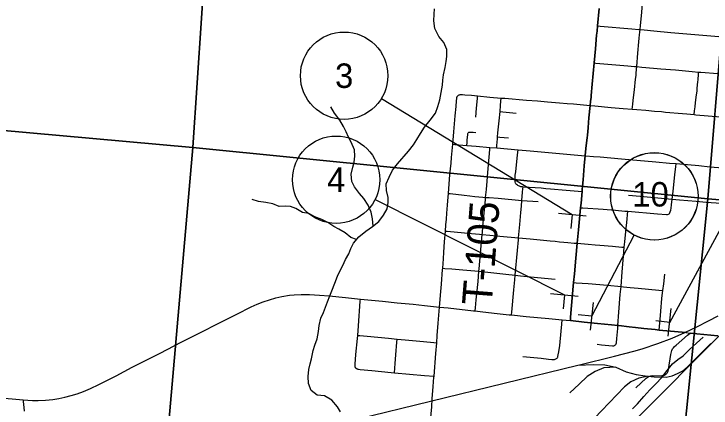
# Model space of a CAD drawing. Extents: x 0 to 1067, y 0 to 440.
# Drawn here: x 268.9 to 348.6, y 95.6 to 140.8 of the extents above; entities that cross this region are included whole.
import ezdxf

# ---------------------------------------------------------------- set-up
doc = ezdxf.new("R2010")
doc.units = 0
for name, color, linetype in [('Default', 7, 'Continuous'), ('GM_X_City_Street', 7, 'Continuous'), ('GM_X_County_Road', 7, 'Continuous'), ('GM_X_Minor_River', 7, 'Continuous'), ('GM_X_Rail_Line', 7, 'Continuous'), ('GM_X_Section', 7, 'Continuous'), ('GM_X_State_Route', 7, 'Continuous'), ('GM_X_Township_Road', 7, 'Continuous'), ('GM_X_Township_Road_Text', 7, 'Continuous'), ('GM_X_US_Route', 7, 'Continuous'), ('SH_Masking', 7, 'Continuous'), ('SH_Text', 7, 'Continuous'), ('SN_P_Signs', 7, 'Continuous')]:
    doc.layers.add(name, color=color, linetype=linetype)

msp = doc.modelspace()

# ---------------------------------------------------------------- linework, layer by layer
at = {"layer": 'Default'}
for q in [(342.702, 104.581), (346.241, 104.236)]:
    msp.add_line((345.76, 104.287), q, dxfattribs=at)
for points in [[(332.539, 105.663), (332.569, 106.043), (332.878, 109.593), (332.917, 110.017), (333.012, 111.021), (333.174, 112.817), (333.319, 114.507), (333.452, 116.059), (333.706, 118.572), (333.761, 119.12), (333.888, 120.454), (333.909, 120.678), (334.011, 121.791), (334.137, 123.39), (334.17, 123.8), (334.242, 124.531), (334.247, 124.578), (334.359, 125.704), (334.444, 126.578), (334.483, 126.899), (334.56, 127.715), (334.617, 128.333), (334.671, 128.886), (334.813, 130.281), (334.859, 130.735), (334.906, 131.249), (334.922, 131.434), (335.027, 132.729), (335.255, 135.163), (335.405, 136.764), (335.544, 138.325), (335.592, 138.808), (335.65, 139.404), (335.843, 141.399)], [(337.977, 105.1), (337.228, 105.175), (335.641, 105.333), (334.136, 105.486), (332.539, 105.663)], [(342.702, 104.581), (342.235, 104.626), (340.941, 104.771), (339.978, 104.883), (339.274, 104.963), (338.088, 105.089), (337.977, 105.1)], [(349.421, 103.902), (346.994, 104.157), (346.241, 104.236)]]:
    msp.add_lwpolyline(points, dxfattribs=at)
at = {"layer": 'GM_X_City_Street'}
for p, q in [((323.327, 125.486), (324.12, 125.418)), ((324.12, 125.418), (326.573, 125.206))]:
    msp.add_line(p, q, dxfattribs=at)
for points in [[(339.625, 129.863), (339.651, 130.082), (339.698, 130.473), (339.778, 131.215), (339.876, 132.058), (340.006, 133.278), (340.05, 133.721), (340.071, 134.016), (340.127, 134.738), (340.261, 136.274), (340.374, 137.568), (340.406, 137.974), (340.447, 138.381), (340.511, 138.974), (340.565, 139.454), (340.638, 140.158), (340.711, 140.948), (340.803, 141.959), (340.845, 142.489), (340.864, 142.724)], [(335.65, 139.404), (335.951, 139.377), (339.567, 139.051), (340.386, 138.984), (340.511, 138.974), (340.978, 138.936), (342.092, 138.84), (344.018, 138.654), (349.998, 138.146), (353.662, 137.79), (354.09, 137.748)], [(335.255, 135.163), (335.464, 135.145), (339.102, 134.824), (339.88, 134.76), (340.127, 134.738), (340.731, 134.686), (342.066, 134.561), (342.88, 134.484), (344.583, 134.346), (346.458, 134.184), (347.218, 134.115), (347.454, 134.094), (349.403, 133.93)], [(346.707, 129.236), (346.754, 129.652), (346.807, 130.116), (346.875, 130.62), (346.983, 131.498), (347.033, 131.934), (347.065, 132.258), (347.133, 132.994), (347.149, 133.209), (347.198, 133.855), (347.218, 134.115)], [(319.754, 131.469), (319.808, 131.494), (319.868, 131.513), (319.931, 131.528), (320.001, 131.538), (320.049, 131.54), (320.099, 131.538), (320.208, 131.533), (320.476, 131.513), (321.234, 131.453), (321.929, 131.379), (323.311, 131.251), (324.627, 131.139), (325.058, 131.103), (327.51, 130.9), (328.774, 130.804), (329.927, 130.71), (331.3, 130.594), (332.192, 130.528), (332.898, 130.474), (334.049, 130.359), (334.813, 130.281), (335.346, 130.227), (337.202, 130.071), (338.572, 129.955), (339.625, 129.863), (340.131, 129.818), (341.172, 129.731), (342.175, 129.642), (342.954, 129.581), (343.433, 129.537), (345.38, 129.351), (345.861, 129.312), (346.707, 129.236), (346.901, 129.218), (351.111, 128.853)], [(321.708, 128.959), (321.797, 129.972), (321.901, 131.079), (321.929, 131.379)], [(324.12, 125.418), (324.142, 125.695), (324.203, 126.457), (324.221, 126.692), (324.257, 127.16), (324.405, 128.526), (324.497, 129.581), (324.549, 130.267), (324.594, 130.771), (324.627, 131.139)], [(324.497, 129.581), (324.806, 129.55), (326.327, 129.401)], [(320.712, 125.709), (320.728, 126.047), (320.744, 126.349), (320.794, 126.934), (320.805, 127.021), (320.824, 127.095), (320.851, 127.15), (320.886, 127.186), (320.927, 127.212), (320.971, 127.23), (321.017, 127.24), (321.108, 127.236), (321.407, 127.215), (321.721, 127.192)], [(324.221, 126.692), (324.48, 126.67), (325.475, 126.585)], [(319.076, 125.847), (319.304, 125.827), (320.712, 125.709)], [(320.712, 125.709), (321.749, 125.622), (323.327, 125.486)], [(321.647, 106.761), (321.684, 107.12), (321.78, 108.053), (321.841, 108.722), (321.981, 110.129), (322.085, 111.318), (322.108, 111.576), (322.345, 114.221), (322.464, 115.529), (322.478, 115.696), (322.539, 116.438), (322.822, 119.512), (322.847, 119.767), (322.939, 120.66), (323.139, 123.085), (323.309, 125.258), (323.327, 125.486)], [(326.474, 121.153), (326.386, 121.222), (326.315, 121.309), (326.265, 121.408), (326.236, 121.533), (326.226, 121.662), (326.226, 121.958), (326.233, 122.18), (326.242, 122.292), (326.291, 122.67), (326.449, 124.258), (326.536, 124.922), (326.573, 125.206)], [(326.573, 125.206), (327.951, 125.087), (329.212, 124.969), (334.242, 124.531)], [(334.242, 124.531), (334.297, 124.526), (335.187, 124.447), (335.968, 124.387), (338.38, 124.181), (342.315, 123.826), (343.875, 123.695), (344.664, 123.625)], [(343.757, 117.836), (343.836, 117.883), (343.883, 117.93), (343.931, 117.993), (343.978, 118.104), (344.034, 118.317), (344.065, 118.523), (344.113, 118.918), (344.19, 119.569), (344.296, 120.447), (344.508, 122.377), (344.619, 123.266), (344.664, 123.625)], [(344.664, 123.625), (347.246, 123.396), (348.507, 123.277), (350.474, 123.111)], [(325.817, 106.304), (325.845, 106.613), (326.079, 109.178), (326.178, 110.315), (326.227, 110.863), (326.48, 113.676), (326.595, 114.901), (326.616, 115.13), (326.755, 116.646), (326.873, 118.018), (326.942, 118.755), (327, 119.413), (327.082, 120.35), (327.11, 120.732), (327.129, 120.988)], [(326.474, 121.153), (326.568, 121.106), (326.67, 121.067), (326.754, 121.043), (326.842, 121.022), (326.925, 121.006), (327.018, 120.995), (327.129, 120.988), (328.519, 120.893), (329.189, 120.848), (329.744, 120.794), (330.263, 120.756), (332.043, 120.608), (333.446, 120.491), (333.888, 120.454)], [(318.583, 120.218), (318.779, 120.195), (320.401, 120.009), (321.02, 119.941), (321.627, 119.881), (322.54, 119.796), (322.847, 119.767), (323.243, 119.74), (324.279, 119.662), (327, 119.413), (328.842, 119.282)], [(339.198, 120.018), (340.534, 119.899), (344.19, 119.569), (345.037, 119.494), (346.917, 119.328), (348.07, 119.234), (349.776, 119.115), (352.306, 118.96), (352.36, 118.957), (353.071, 118.894), (353.774, 118.823), (354.397, 118.748), (354.727, 118.699)], [(333.706, 118.572), (333.97, 118.554), (336.306, 118.402), (337.713, 118.293), (338.788, 118.198), (339.106, 118.168), (342.494, 117.882), (343.534, 117.804), (343.647, 117.812), (343.757, 117.836)], [(337.977, 105.1), (338.069, 106.614), (338.252, 108.664), (338.351, 109.564), (338.471, 111.259), (338.619, 113.05), (338.707, 114.056), (338.76, 114.664), (338.922, 116.258), (338.986, 116.871), (339.106, 118.168)], [(318.248, 115.901), (318.437, 115.884), (321.21, 115.633), (322.138, 115.559), (322.464, 115.529), (323.325, 115.449), (324.475, 115.333), (326.616, 115.13), (327.925, 115.019), (330.217, 114.791), (330.809, 114.736), (331.287, 114.683), (331.805, 114.635), (332.249, 114.595), (332.991, 114.533), (333.319, 114.507), (334.587, 114.407), (335.368, 114.35), (335.924, 114.301), (337.357, 114.171), (338.446, 114.079), (338.707, 114.056)], [(317.934, 111.65), (318.187, 111.634), (318.966, 111.585), (320.243, 111.479), (322.085, 111.318), (325.156, 110.971), (326.227, 110.863), (326.826, 110.801), (327.976, 110.68), (330.785, 110.397)], [(342.702, 104.581), (342.734, 104.976), (342.836, 106.233), (342.875, 106.734), (343.006, 108.177), (343.084, 108.846), (343.117, 109.098), (343.218, 109.876), (343.336, 110.977)], [(332.917, 110.017), (333.2, 109.998), (334.576, 109.904), (336.797, 109.714), (338.351, 109.564), (338.606, 109.537), (339.384, 109.465), (340.287, 109.366), (341.494, 109.253), (342.644, 109.143), (343.117, 109.098)], [(330.965, 101.313), (331.012, 101.354), (331.07, 101.418), (331.099, 101.47), (331.122, 101.541), (331.163, 101.72), (331.227, 102.09), (331.327, 102.792), (331.497, 104.456), (331.573, 105.264), (331.617, 105.747)], [(335.619, 102.957), (336.098, 102.894), (336.949, 102.808), (337.357, 102.776), (337.428, 102.776), (337.505, 102.788), (337.572, 102.801), (337.634, 102.832), (337.705, 102.881), (337.753, 102.937), (337.787, 103.002), (337.81, 103.107), (337.869, 103.59), (337.953, 104.766), (337.977, 105.1)], [(343.786, 100.069), (344.054, 101.778), (344.114, 102.069), (344.168, 102.251), (344.237, 102.414), (344.326, 102.557), (344.449, 102.69), (344.627, 102.843), (345.947, 103.982), (346.241, 104.236)], [(327.103, 101.554), (329.202, 101.351), (330.05, 101.259), (330.424, 101.223), (330.524, 101.215), (330.635, 101.209), (330.722, 101.215), (330.809, 101.232), (330.896, 101.267), (330.965, 101.313)], [(340.038, 97.946), (341.231, 99.086), (341.452, 99.224), (341.621, 99.302), (341.764, 99.341), (341.911, 99.358), (342.948, 99.349), (343.044, 99.354), (343.153, 99.366), (343.219, 99.378), (343.303, 99.406), (343.387, 99.445), (343.473, 99.507), (343.53, 99.551), (343.582, 99.605), (343.626, 99.664), (343.669, 99.73), (343.725, 99.862), (343.786, 100.069)], [(269.932, 96.575), (269.944, 96.412), (269.999, 95.698), (270.042, 95.286)]]:
    msp.add_lwpolyline(points, dxfattribs=at)
at = {"layer": 'GM_X_County_Road'}
for p, q in [((317.424, 105.354), (317.559, 107.21)), ((317.316, 103.968), (317.424, 105.354)), ((317.246, 103.123), (317.316, 103.968))]:
    msp.add_line(p, q, dxfattribs=at)
for points in [[(316.94, 99.297), (317.146, 101.896), (317.246, 103.123)], [(316.492, 93.735), (316.615, 94.973), (316.68, 95.792), (316.744, 96.684), (316.851, 98.118), (316.932, 99.195), (316.94, 99.297)]]:
    msp.add_lwpolyline(points, dxfattribs=at)
at = {"layer": 'GM_X_Minor_River'}
for points in [[(306.238, 95.195), (305.884, 95.771), (305.237, 96.533), (304.403, 97.049), (303.585, 97.131), (302.865, 97.645), (302.583, 98.47), (302.529, 99.245), (302.634, 100.064), (302.759, 100.7), (302.906, 101.29), (303.128, 102.22), (303.321, 102.855), (303.561, 103.557), (303.735, 104.397), (303.816, 105.079), (303.99, 105.942), (304.297, 106.575), (304.513, 107.186), (304.752, 107.82), (305.037, 108.476), (305.252, 109.065), (305.609, 109.925), (305.897, 110.74), (306.18, 111.328), (306.51, 111.983), (306.795, 112.639), (307.194, 113.316), (307.433, 113.927), (307.739, 114.514), (308.321, 115.233), (309.13, 115.88), (309.913, 116.414), (310.63, 117.017), (311.166, 117.714), (311.566, 118.437), (311.693, 119.186), (311.68, 119.756), (311.489, 120.534), (311.48, 121.332), (311.789, 122.078), (312.19, 122.869), (312.75, 123.589), (314.028, 125.071), (314.587, 125.768), (314.985, 126.399), (315.407, 127.075), (315.853, 127.82), (316.481, 128.584), (317.11, 129.393), (317.375, 130.163), (317.593, 130.912), (317.767, 131.775), (317.896, 132.615), (317.952, 133.184), (318.031, 133.798), (318.204, 134.615), (318.331, 135.32), (318.409, 135.888), (318.423, 136.685), (318.05, 137.489), (317.493, 138.182), (317.031, 139.101), (316.91, 139.992), (316.945, 140.72), (317.002, 141.334)], [(309.961, 116.454), (309.906, 117.303), (309.737, 118.057), (309.388, 118.884), (308.9, 119.644), (308.432, 120.221), (307.853, 120.983), (307.522, 121.581), (307.446, 122.425), (307.665, 123.219), (307.789, 123.81), (307.892, 124.491), (307.837, 125.221), (307.465, 126.093), (307.156, 126.668), (306.87, 127.266), (306.585, 127.886), (306.165, 128.599), (305.542, 129.407), (305.122, 130.143)], [(308.085, 114.941), (307.432, 115.157), (306.781, 115.715), (306.059, 116.115), (305.473, 116.421), (304.775, 116.888), (304.121, 117.241), (303.306, 117.551), (302.607, 117.928), (301.903, 118.031), (301.113, 118.477), (300.503, 118.715), (299.911, 118.748), (299.228, 118.737), (298.481, 119.023), (297.687, 119.173), (296.869, 119.278), (296.144, 119.518)], [(339.654, 95.563), (340.233, 96.145), (340.954, 96.953), (341.65, 97.739), (342.323, 98.411), (343.019, 99.151), (343.625, 99.938), (344.231, 100.703), (344.854, 101.194), (345.431, 101.64), (346.172, 102.333), (346.96, 103.072), (347.746, 103.765)]]:
    msp.add_lwpolyline(points, dxfattribs=at)
at = {"layer": 'GM_X_Rail_Line'}
for points in [[(356.37, 110.755), (341.091, 95.394), (330.427, 84.614)], [(333.402, 100.541), (333.584, 100.585), (337.589, 101.572), (339.801, 102.14), (340.767, 102.416), (342.562, 103.025), (344.204, 103.657), (345.634, 104.295), (347.026, 104.937), (348.344, 105.612), (349.451, 106.204)], [(341.432, 99.29), (342.145, 99.224), (343.507, 99.165), (344.177, 99.342), (344.809, 99.599), (345.4, 99.894), (345.933, 100.368), (348.616, 103.051)], [(287.082, 89.176), (308.109, 94.369), (333.402, 100.541)], [(333.402, 100.541), (335.201, 100.644), (336.483, 100.585), (337.726, 100.309)], [(337.726, 100.309), (336.385, 100.25), (335.359, 99.835), (334.451, 99.243), (333.563, 98.395), (332.498, 97.389)], [(337.726, 100.309), (338.929, 99.796), (340.054, 99.48), (341.08, 99.322), (341.432, 99.29)], [(341.432, 99.29), (340.389, 99.066), (339.442, 98.652), (338.732, 98.06), (336.108, 95.337), (333.149, 92.22)]]:
    msp.add_lwpolyline(points, dxfattribs=at)
at = {"layer": 'GM_X_Section'}
for points in [[(230.143, 191.616), (293.305, 184.745), (289.359, 125.481), (225.317, 131.247)], [(293.305, 184.745), (353.183, 178.942), (348.264, 119.585), (289.359, 125.481)], [(353.183, 178.942), (415.565, 173.729), (410.18, 114.397), (348.264, 119.585)], [(225.317, 131.247), (289.359, 125.481), (286.308, 90.531), (282.115, 64.529), (220.613, 71.485)], [(289.359, 125.481), (348.264, 119.585), (342.16, 58.91), (282.115, 64.529), (286.308, 90.531)], [(410.18, 114.397), (404.583, 52.958), (342.16, 58.91), (348.264, 119.585)]]:
    msp.add_lwpolyline(points, close=True, dxfattribs=at)
at = {"layer": 'GM_X_State_Route'}
for p, q in [((342.702, 104.581), (345.76, 104.287)), ((345.76, 104.287), (346.241, 104.236))]:
    msp.add_line(p, q, dxfattribs=at)
for points in [[(335.843, 141.399), (335.65, 139.404), (335.592, 138.808), (335.544, 138.325), (335.405, 136.764), (335.255, 135.163), (335.027, 132.729), (334.922, 131.434), (334.906, 131.249), (334.859, 130.735), (334.813, 130.281), (334.671, 128.886), (334.617, 128.333), (334.56, 127.715), (334.483, 126.899), (334.444, 126.578), (334.359, 125.704), (334.247, 124.578), (334.242, 124.531), (334.17, 123.8), (334.137, 123.39), (334.011, 121.791), (333.909, 120.678), (333.888, 120.454), (333.761, 119.12), (333.706, 118.572), (333.452, 116.059), (333.319, 114.507), (333.174, 112.817), (333.012, 111.021), (332.917, 110.017), (332.878, 109.593), (332.569, 106.043), (332.539, 105.663)], [(332.539, 105.663), (334.136, 105.486), (335.641, 105.333), (337.228, 105.175), (337.977, 105.1)], [(337.977, 105.1), (338.088, 105.089), (339.274, 104.963), (339.978, 104.883), (340.941, 104.771), (342.235, 104.626), (342.702, 104.581)], [(346.241, 104.236), (346.994, 104.157), (349.421, 103.902)]]:
    msp.add_lwpolyline(points, dxfattribs=at)
at = {"layer": 'GM_X_Township_Road'}
for points in [[(319.076, 125.847), (319.198, 127.248), (319.353, 129.104), (319.456, 130.179), (319.512, 130.833), (319.533, 131.068), (319.547, 131.148), (319.569, 131.227), (319.596, 131.294), (319.614, 131.33), (319.635, 131.365), (319.662, 131.394), (319.718, 131.444), (319.754, 131.469)], [(318.583, 120.218), (318.768, 122.396), (318.888, 123.694), (318.944, 124.323), (319.076, 125.847)], [(318.248, 115.901), (318.308, 116.616), (318.351, 117.258), (318.396, 117.956), (318.437, 118.399), (318.472, 118.882), (318.51, 119.365), (318.583, 120.218)], [(317.934, 111.65), (318.014, 112.728), (318.063, 113.507), (318.143, 114.658), (318.248, 115.901)], [(317.559, 107.21), (317.714, 108.98), (317.793, 109.833), (317.924, 111.503), (317.934, 111.65)], [(308.21, 103.961), (308.3, 105.058), (308.507, 107.87), (308.526, 108.121)], [(307.964, 100.255), (307.937, 100.299), (307.92, 100.343), (307.909, 100.393), (307.904, 100.439), (307.904, 100.486), (307.907, 100.546), (307.917, 100.669), (308.011, 101.77), (308.182, 103.618), (308.21, 103.961)], [(308.21, 103.961), (308.453, 103.94), (309.304, 103.867), (311.746, 103.64), (312.708, 103.548)], [(312.431, 99.696), (312.502, 100.747), (312.581, 101.748), (312.683, 103.191), (312.708, 103.548)], [(312.708, 103.548), (313.65, 103.459), (315.727, 103.266), (316.93, 103.153), (317.246, 103.123)], [(307.964, 100.255), (307.993, 100.222), (308.03, 100.196), (308.065, 100.173), (308.12, 100.146), (308.168, 100.129), (308.224, 100.117), (308.307, 100.102), (308.492, 100.077), (309.836, 99.959), (312.028, 99.735), (312.431, 99.696)], [(312.431, 99.696), (315.835, 99.381), (316.94, 99.297)]]:
    msp.add_lwpolyline(points, dxfattribs=at)
at = {"layer": 'GM_X_US_Route'}
for p, q in [((342.702, 104.581), (345.76, 104.287)), ((345.76, 104.287), (346.241, 104.236))]:
    msp.add_line(p, q, dxfattribs=at)
for points in [[(266.931, 96.844), (269.932, 96.575), (271.007, 96.524), (271.645, 96.518), (272.504, 96.559), (273.324, 96.64), (274.027, 96.745), (274.688, 96.879), (275.413, 97.066), (276.093, 97.272), (276.833, 97.539), (277.625, 97.874), (278.57, 98.324), (280.561, 99.352), (282.417, 100.311), (285.596, 101.931), (288.018, 103.177), (290.382, 104.367), (292.171, 105.29), (294.363, 106.404), (296.035, 107.224), (296.712, 107.53), (297.402, 107.805), (298.105, 108.043), (298.856, 108.253), (299.543, 108.408), (300.422, 108.552), (300.938, 108.601), (301.753, 108.639), (302.682, 108.631), (303.834, 108.575), (304.946, 108.481), (306.799, 108.285), (308.526, 108.121), (311.029, 107.883), (312.734, 107.709), (314.552, 107.536), (315.847, 107.391), (317.559, 107.21)], [(317.559, 107.21), (318.54, 107.103), (321.44, 106.787), (321.647, 106.761), (321.918, 106.726), (322.507, 106.651), (324.173, 106.477), (325.542, 106.331), (325.817, 106.304), (327.468, 106.141), (330.061, 105.881), (331.617, 105.747), (332.076, 105.705), (332.539, 105.663)], [(332.539, 105.663), (334.136, 105.486), (335.641, 105.333), (337.228, 105.175), (337.977, 105.1)], [(337.977, 105.1), (338.088, 105.089), (339.274, 104.963), (339.978, 104.883), (340.941, 104.771), (342.235, 104.626), (342.702, 104.581)], [(346.241, 104.236), (346.994, 104.157), (349.421, 103.902)]]:
    msp.add_lwpolyline(points, dxfattribs=at)
at = {"layer": 'SH_Masking'}
for centre in [(306.656, 133.694), (305.745, 121.789), (342.163, 119.875)]:
    msp.add_circle(centre, 5, dxfattribs=at)
at = {"layer": 'SH_Text'}
for p, q in [((310.927, 131.095), (332.765, 117.809)), ((310.208, 119.536), (331.854, 108.611)), ((343.906, 105.458), (351.352, 119.2)), ((335.013, 106.147), (339.841, 115.447))]:
    msp.add_line(p, q, dxfattribs=at)
for centre in [(306.656, 133.694), (305.745, 121.789), (342.144, 119.884)]:
    msp.add_circle(centre, 5, dxfattribs=at)
at = {"layer": 'SN_P_Signs'}
for p, q in [((331.172, 117.963), (334.357, 117.655)), ((332.765, 117.809), (332.611, 116.217)), ((330.261, 108.765), (333.446, 108.457)), ((331.854, 108.611), (331.7, 107.018)), ((334.833, 104.558), (335.192, 107.737)), ((343.727, 103.868), (344.086, 107.048)), ((335.013, 106.147), (333.423, 106.327)), ((343.906, 105.458), (342.316, 105.637))]:
    msp.add_line(p, q, dxfattribs=at)

# ---------------------------------------------------------------- texts
at = {"layer": 'GM_X_Township_Road_Text'}
msp.add_text('T-105', height=3.4091, rotation=85.51474, dxfattribs=at).set_placement((323.527, 107.307))
at = {"layer": 'SH_Text'}
for s, p in [('3', (305.618, 132.294)), ('4', (304.708, 120.389))]:
    msp.add_text(s, height=2.8, dxfattribs=at).set_placement(p)
msp.add_text('10', height=2.8, rotation=360, dxfattribs=at).set_placement((339.631, 118.716))

doc.saveas('drawing.dxf')
